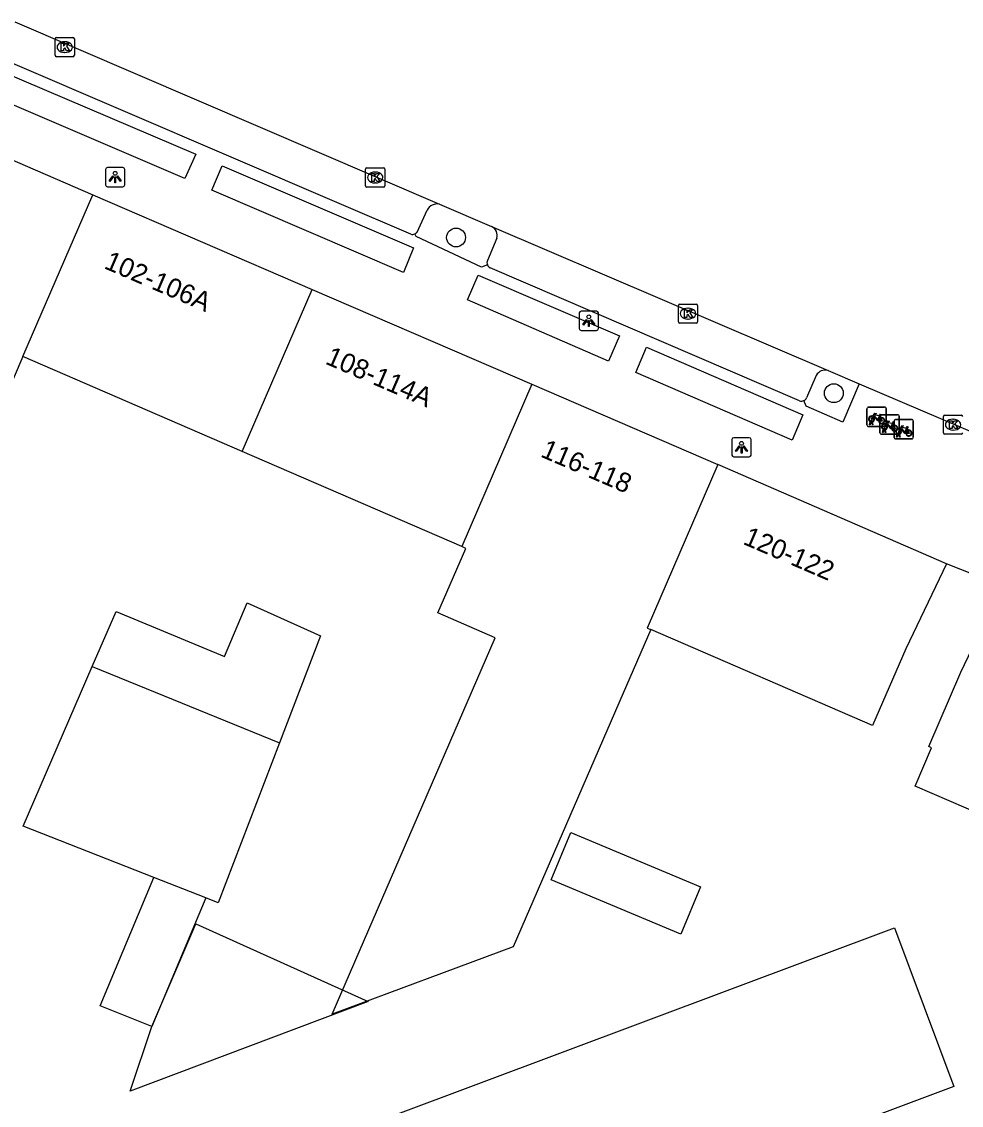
# Model space of a CAD drawing. Extents: x 161801 to 162379, y 382315 to 382832.
# Drawn here: x 162214 to 162262.8, y 382570.8 to 382627.1 of the extents above; entities that cross this region are included whole.
import ezdxf

# ---------------------------------------------------------------- set-up
doc = ezdxf.new("R2010")
doc.units = 0
for name, color, linetype in [('IMGEO_Boom', 7, 'Continuous'), ('IMGEO_Fietsenrek', 7, 'Continuous'), ('IMGEO_Kolk', 7, 'Continuous'), ('IMGEO_Lichtpunt', 7, 'Continuous'), ('IMGEO_Pand', 7, 'Continuous'), ('IMGEO_Pand_nummerreeks', 7, 'Continuous'), ('IMGEO_Pand_vergunning_verleend', 7, 'Continuous'), ('IMGEO_Parkeervlak_open', 7, 'Continuous'), ('IMGEO_Rijbaan_lokaal_gesloten', 7, 'Continuous'), ('IMGEO_Voetpad_open', 7, 'Continuous')]:
    doc.layers.add(name, color=color, linetype=linetype)

msp = doc.modelspace()

# ---------------------------------------------------------------- linework, layer by layer
at = {"layer": 'IMGEO_Boom'}
for centre in [(162236.594, 382615.904), (162256.208, 382607.818)]:
    msp.add_circle(centre, 0.489, dxfattribs=at)
at = {"layer": 'IMGEO_Fietsenrek'}
for p, q in [((162258.004, 382607.092), (162258.845, 382607.092)), ((162258.845, 382607.092), (162258.004, 382607.092)), ((162257.929, 382606.167), (162257.929, 382607.008)), ((162257.929, 382607.008), (162257.929, 382606.167)), ((162258.603, 382605.768), (162258.603, 382606.609)), ((162258.603, 382606.609), (162258.603, 382605.768)), ((162258.616, 382606.641), (162258.652, 382606.546)), ((162258.678, 382606.693), (162259.519, 382606.693)), ((162259.519, 382606.693), (162258.678, 382606.693)), ((162258.929, 382607.017), (162258.929, 382606.176)), ((162258.929, 382606.176), (162258.929, 382607.017)), ((162259.603, 382606.618), (162259.603, 382605.777)), ((162259.603, 382605.777), (162259.603, 382606.618)), ((162258.854, 382606.092), (162258.013, 382606.092)), ((162258.013, 382606.092), (162258.854, 382606.092)), ((162258.056, 382606.176), (162258.095, 382606.336)), ((162258.09, 382606.176), (162258.056, 382606.176)), ((162258.125, 382606.324), (162258.09, 382606.176)), ((162258.167, 382606.348), (162258.166, 382606.352)), ((162258.208, 382606.176), (162258.174, 382606.318)), ((162258.198, 382606.359), (162258.199, 382606.352)), ((162258.206, 382606.322), (162258.241, 382606.176)), ((162258.241, 382606.176), (162258.208, 382606.176)), ((162258.872, 382605.96), (162258.873, 382605.953)), ((162259.29, 382606.242), (162259.326, 382606.147)), ((162259.334, 382605.523), (162259.334, 382606.364)), ((162259.334, 382606.364), (162259.334, 382605.523)), ((162259.409, 382606.448), (162260.25, 382606.448)), ((162260.25, 382606.448), (162259.409, 382606.448)), ((162260.021, 382605.997), (162260.057, 382605.902)), ((162260.334, 382606.373), (162260.334, 382605.532)), ((162260.334, 382605.532), (162260.334, 382606.373)), ((162259.528, 382605.693), (162258.687, 382605.693)), ((162258.687, 382605.693), (162259.528, 382605.693)), ((162258.73, 382605.777), (162258.769, 382605.937)), ((162258.764, 382605.777), (162258.73, 382605.777)), ((162258.799, 382605.925), (162258.764, 382605.777)), ((162258.841, 382605.949), (162258.84, 382605.953)), ((162258.882, 382605.777), (162258.848, 382605.919)), ((162258.88, 382605.923), (162258.915, 382605.777)), ((162258.915, 382605.777), (162258.882, 382605.777)), ((162260.259, 382605.448), (162259.418, 382605.448)), ((162259.418, 382605.448), (162260.259, 382605.448)), ((162259.461, 382605.532), (162259.5, 382605.692)), ((162259.495, 382605.532), (162259.461, 382605.532)), ((162259.53, 382605.68), (162259.495, 382605.532)), ((162259.572, 382605.704), (162259.571, 382605.708)), ((162259.613, 382605.532), (162259.579, 382605.674)), ((162259.603, 382605.715), (162259.604, 382605.708)), ((162259.611, 382605.678), (162259.646, 382605.532)), ((162259.646, 382605.532), (162259.613, 382605.532))]:
    msp.add_line(p, q, dxfattribs=at)
for points in [[(162258.263, 382606.566), (162258.211, 382606.476), (162258.171, 382606.451), (162258.172, 382606.498), (162258.227, 382606.592)], [(162258.242, 382606.618), (162258.337, 382606.782), (162258.423, 382606.768), (162258.425, 382606.759), (162258.369, 382606.748), (162258.342, 382606.703), (162258.598, 382606.662)], [(162258.538, 382606.374), (162258.488, 382606.374), (162258.297, 382606.625), (162258.278, 382606.593)], [(162258.585, 382606.637), (162258.328, 382606.678), (162258.311, 382606.649), (162258.478, 382606.429), (162258.585, 382606.637)], [(162258.633, 382606.539), (162258.603, 382606.616), (162258.494, 382606.398), (162258.537, 382606.398)], [(162258.663, 382606.518), (162258.718, 382606.373), (162258.568, 382606.373)], [(162258.598, 382606.662), (162258.623, 382606.711), (162258.617, 382606.715), (162258.594, 382606.719), (162258.582, 382606.726), (162258.581, 382606.729), (162258.583, 382606.734), (162258.678, 382606.719), (162258.68, 382606.709), (162258.67, 382606.696), (162258.658, 382606.69), (162258.644, 382606.696), (162258.616, 382606.641)], [(162258.567, 382606.398), (162258.687, 382606.397), (162258.643, 382606.511)], [(162258.937, 382606.167), (162258.885, 382606.077), (162258.845, 382606.052), (162258.846, 382606.099), (162258.901, 382606.193)], [(162258.916, 382606.219), (162259.011, 382606.383), (162259.097, 382606.369), (162259.099, 382606.36), (162259.043, 382606.349), (162259.016, 382606.304), (162259.272, 382606.263)], [(162259.212, 382605.975), (162259.162, 382605.975), (162258.971, 382606.226), (162258.952, 382606.194)], [(162259.259, 382606.238), (162259.002, 382606.279), (162258.985, 382606.25), (162259.152, 382606.03), (162259.259, 382606.238)], [(162259.307, 382606.14), (162259.277, 382606.217), (162259.168, 382605.999), (162259.211, 382605.999)], [(162259.241, 382605.999), (162259.361, 382605.998), (162259.317, 382606.112)], [(162259.337, 382606.119), (162259.392, 382605.974), (162259.242, 382605.974)], [(162259.272, 382606.263), (162259.297, 382606.312), (162259.291, 382606.316), (162259.268, 382606.32), (162259.256, 382606.327), (162259.255, 382606.33), (162259.257, 382606.335), (162259.352, 382606.32), (162259.354, 382606.31), (162259.344, 382606.297), (162259.332, 382606.291), (162259.318, 382606.297), (162259.29, 382606.242)], [(162259.647, 382605.974), (162259.742, 382606.138), (162259.828, 382606.124), (162259.83, 382606.115), (162259.774, 382606.104), (162259.747, 382606.059), (162260.003, 382606.018)], [(162259.943, 382605.73), (162259.893, 382605.73), (162259.702, 382605.981), (162259.683, 382605.949)], [(162259.99, 382605.993), (162259.733, 382606.034), (162259.716, 382606.005), (162259.883, 382605.785), (162259.99, 382605.993)], [(162260.038, 382605.895), (162260.008, 382605.972), (162259.899, 382605.754), (162259.942, 382605.754)], [(162260.003, 382606.018), (162260.028, 382606.067), (162260.022, 382606.071), (162259.999, 382606.075), (162259.987, 382606.082), (162259.986, 382606.085), (162259.988, 382606.09), (162260.083, 382606.075), (162260.085, 382606.065), (162260.075, 382606.052), (162260.063, 382606.046), (162260.049, 382606.052), (162260.021, 382605.997)], [(162259.668, 382605.922), (162259.616, 382605.832), (162259.576, 382605.807), (162259.577, 382605.854), (162259.632, 382605.948)], [(162259.972, 382605.754), (162260.092, 382605.753), (162260.048, 382605.867)], [(162260.068, 382605.874), (162260.123, 382605.729), (162259.973, 382605.729)]]:
    msp.add_lwpolyline(points, dxfattribs=at)
for centre, radius, start, end in [((162258.007, 382607.014), 0.0779, 92.4484, 184.2845), ((162258.007, 382607.014), 0.0779, 92.4484, 184.2845), ((162258.851, 382607.014), 0.0779, 2.4484, 94.2845), ((162258.851, 382607.014), 0.0779, 2.4484, 94.2845), ((162258.169, 382606.477), 0.159, 62.6766, 242.1369), ((162258.169, 382606.477), 0.129, 63.3192, 238.903), ((162258.169, 382606.477), 0.129, 283.6043, 43.4302), ((162258.169, 382606.477), 0.159, 283.5766, 46.6042), ((162258.696, 382606.393), 0.159, 113.3408, 178.3217), ((162258.696, 382606.393), 0.159, 187.0065, 105.7708), ((162258.696, 382606.393), 0.129, 188.6715, 104.5883), ((162258.681, 382606.615), 0.0779, 92.4484, 184.2845), ((162258.681, 382606.615), 0.0779, 92.4484, 184.2845), ((162259.525, 382606.615), 0.0779, 2.4484, 94.2845), ((162259.525, 382606.615), 0.0779, 2.4484, 94.2845), ((162258.007, 382606.17), 0.0779, 182.4484, 274.2845), ((162258.007, 382606.17), 0.0779, 182.4484, 274.2845), ((162258.149, 382606.348), 0.0499, 12.8025, 158.6934), ((162258.169, 382606.477), 0.159, 253.9967, 271.7867), ((162258.149, 382606.348), 0.0174, 12.8025, 163.4502), ((162258.169, 382606.477), 0.129, 253.415, 269.0204), ((162258.696, 382606.393), 0.129, 113.923, 177.9556), ((162258.843, 382606.078), 0.159, 62.6766, 242.1369), ((162258.843, 382606.078), 0.129, 63.3192, 238.903), ((162258.823, 382605.949), 0.0499, 12.8025, 158.6934), ((162258.823, 382605.949), 0.0174, 12.8025, 163.4502), ((162258.851, 382606.17), 0.0779, 272.4484, 4.2845), ((162258.851, 382606.17), 0.0779, 272.4484, 4.2845), ((162258.843, 382606.078), 0.129, 283.6043, 43.4302), ((162258.843, 382606.078), 0.159, 283.5766, 46.6042), ((162259.37, 382605.994), 0.159, 113.3408, 178.3217), ((162259.37, 382605.994), 0.159, 187.0065, 105.7708), ((162259.37, 382605.994), 0.129, 113.923, 177.9556), ((162259.37, 382605.994), 0.129, 188.6715, 104.5883), ((162259.412, 382606.37), 0.0779, 92.4484, 184.2845), ((162259.412, 382606.37), 0.0779, 92.4484, 184.2845), ((162259.574, 382605.833), 0.159, 62.6766, 242.1369), ((162259.574, 382605.833), 0.129, 63.3192, 238.903), ((162260.256, 382606.37), 0.0779, 2.4484, 94.2845), ((162260.256, 382606.37), 0.0779, 2.4484, 94.2845), ((162258.681, 382605.771), 0.0779, 182.4484, 274.2845), ((162258.681, 382605.771), 0.0779, 182.4484, 274.2845), ((162258.843, 382606.078), 0.159, 253.9967, 271.7867), ((162258.843, 382606.078), 0.129, 253.415, 269.0204), ((162259.412, 382605.526), 0.0779, 182.4484, 274.2845), ((162259.412, 382605.526), 0.0779, 182.4484, 274.2845), ((162259.554, 382605.704), 0.0499, 12.8025, 158.6934), ((162259.525, 382605.771), 0.0779, 272.4484, 4.2845), ((162259.525, 382605.771), 0.0779, 272.4484, 4.2845), ((162259.574, 382605.833), 0.159, 253.9967, 271.7867), ((162259.554, 382605.704), 0.0174, 12.8025, 163.4502), ((162259.574, 382605.833), 0.129, 253.415, 269.0204), ((162259.574, 382605.833), 0.129, 283.6043, 43.4302), ((162259.574, 382605.833), 0.159, 283.5766, 46.6042), ((162260.101, 382605.749), 0.159, 113.3408, 178.3217), ((162260.101, 382605.749), 0.159, 187.0065, 105.7708), ((162260.101, 382605.749), 0.129, 113.923, 177.9556), ((162260.101, 382605.749), 0.129, 188.6715, 104.5883), ((162260.256, 382605.526), 0.0779, 272.4484, 4.2845), ((162260.256, 382605.526), 0.0779, 272.4484, 4.2845)]:
    msp.add_arc(centre, radius, start, end, dxfattribs=at)
at = {"layer": 'IMGEO_Kolk'}
for p, q in [((162215.778, 382625.366), (162215.778, 382626.218)), ((162215.853, 382626.292), (162216.705, 382626.292)), ((162216.779, 382626.218), (162216.779, 382625.366)), ((162216.266, 382626.072), (162216.291, 382626.072)), ((162216.705, 382625.292), (162215.853, 382625.292)), ((162216.289, 382625.512), (162216.264, 382625.512)), ((162231.971, 382619.519), (162232.823, 382619.519)), ((162231.896, 382618.593), (162231.896, 382619.445)), ((162232.384, 382619.299), (162232.409, 382619.299)), ((162232.897, 382619.445), (162232.897, 382618.593)), ((162232.823, 382618.519), (162231.971, 382618.519)), ((162232.407, 382618.739), (162232.382, 382618.739)), ((162248.137, 382611.523), (162248.137, 382612.375)), ((162248.212, 382612.449), (162249.064, 382612.449)), ((162248.625, 382612.229), (162248.65, 382612.229)), ((162249.138, 382612.375), (162249.138, 382611.523)), ((162248.648, 382611.669), (162248.623, 382611.669)), ((162249.064, 382611.449), (162248.212, 382611.449)), ((162261.901, 382605.757), (162261.901, 382606.609)), ((162261.976, 382606.683), (162262.828, 382606.683)), ((162262.389, 382606.463), (162262.414, 382606.463)), ((162262.828, 382605.683), (162261.976, 382605.683)), ((162262.412, 382605.903), (162262.387, 382605.903))]:
    msp.add_line(p, q, dxfattribs=at)
for points in [[(162215.778, 382625.366), (162215.778, 382626.218)], [(162215.853, 382626.292), (162216.705, 382626.292)], [(162216.779, 382626.218), (162216.779, 382625.366)], [(162216.099, 382625.992), (162216.222, 382625.992), (162216.222, 382625.841), (162216.352, 382625.992), (162216.516, 382625.992), (162216.37, 382625.841), (162216.523, 382625.592), (162216.371, 382625.592), (162216.286, 382625.756), (162216.222, 382625.689), (162216.222, 382625.592), (162216.099, 382625.592), (162216.099, 382625.992)], [(162216.705, 382625.292), (162215.853, 382625.292)], [(162231.971, 382619.519), (162232.823, 382619.519)], [(162231.896, 382618.593), (162231.896, 382619.445)], [(162232.217, 382619.219), (162232.34, 382619.219), (162232.34, 382619.068), (162232.47, 382619.219), (162232.634, 382619.219), (162232.488, 382619.068), (162232.641, 382618.819), (162232.489, 382618.819), (162232.404, 382618.983), (162232.34, 382618.916), (162232.34, 382618.819), (162232.217, 382618.819), (162232.217, 382619.219)], [(162232.897, 382619.445), (162232.897, 382618.593)], [(162232.823, 382618.519), (162231.971, 382618.519)], [(162248.137, 382611.523), (162248.137, 382612.375)], [(162248.212, 382612.449), (162249.064, 382612.449)], [(162248.458, 382612.149), (162248.581, 382612.149), (162248.581, 382611.998), (162248.711, 382612.149), (162248.875, 382612.149), (162248.729, 382611.998), (162248.882, 382611.749), (162248.73, 382611.749), (162248.645, 382611.913), (162248.581, 382611.846), (162248.581, 382611.749), (162248.458, 382611.749), (162248.458, 382612.149)], [(162249.138, 382612.375), (162249.138, 382611.523)], [(162249.064, 382611.449), (162248.212, 382611.449)], [(162261.901, 382605.757), (162261.901, 382606.609)], [(162261.976, 382606.683), (162262.828, 382606.683)], [(162262.222, 382606.383), (162262.345, 382606.383), (162262.345, 382606.232), (162262.475, 382606.383), (162262.639, 382606.383), (162262.493, 382606.232), (162262.646, 382605.983), (162262.494, 382605.983), (162262.409, 382606.147), (162262.345, 382606.08), (162262.345, 382605.983), (162262.222, 382605.983), (162262.222, 382606.383)], [(162262.828, 382605.683), (162261.976, 382605.683)]]:
    msp.add_lwpolyline(points, dxfattribs=at)
for centre, start, end in [((162215.855, 382626.216), 91.552, 178.448), ((162215.855, 382626.216), 91.552, 178.448), ((162216.703, 382626.216), 1.552, 88.448), ((162216.703, 382626.216), 1.552, 88.448), ((162215.855, 382625.368), 181.552, 268.448), ((162215.855, 382625.368), 181.552, 268.448), ((162216.703, 382625.368), 271.552, 358.448), ((162216.703, 382625.368), 271.552, 358.448), ((162231.973, 382619.443), 91.552, 178.448), ((162231.973, 382619.443), 91.552, 178.448), ((162232.821, 382619.443), 1.552, 88.448), ((162232.821, 382619.443), 1.552, 88.448), ((162231.973, 382618.595), 181.552, 268.448), ((162231.973, 382618.595), 181.552, 268.448), ((162232.821, 382618.595), 271.552, 358.448), ((162232.821, 382618.595), 271.552, 358.448), ((162248.214, 382612.373), 91.552, 178.448), ((162248.214, 382612.373), 91.552, 178.448), ((162249.062, 382612.373), 1.552, 88.448), ((162249.062, 382612.373), 1.552, 88.448), ((162248.214, 382611.525), 181.552, 268.448), ((162248.214, 382611.525), 181.552, 268.448), ((162249.062, 382611.525), 271.552, 358.448), ((162249.062, 382611.525), 271.552, 358.448), ((162261.978, 382606.607), 91.552, 178.448), ((162261.978, 382606.607), 91.552, 178.448), ((162262.826, 382606.607), 1.552, 88.448), ((162262.826, 382606.607), 1.552, 88.448), ((162261.978, 382605.759), 181.552, 268.448), ((162261.978, 382605.759), 181.552, 268.448), ((162262.826, 382605.759), 271.552, 358.448), ((162262.826, 382605.759), 271.552, 358.448)]:
    msp.add_arc(centre, 0.0765, start, end, dxfattribs=at)
for centre, major_axis, ratio, start_param, end_param in [((162216.265, 382625.792), (-0.387, 0.002), 0.722429, 4.712389, 7.853982), ((162216.29, 382625.792), (-0.39, 0.002), 0.717154, 1.570796, 4.712389), ((162232.383, 382619.019), (-0.387, 0.002), 0.722429, 4.712389, 7.853982), ((162232.408, 382619.019), (-0.39, 0.002), 0.717154, 1.570796, 4.712389), ((162248.624, 382611.949), (-0.387, 0.002), 0.722429, 4.712389, 7.853982), ((162248.649, 382611.949), (-0.39, 0.002), 0.717154, 1.570796, 4.712389), ((162262.388, 382606.183), (-0.387, 0.002), 0.722429, 4.712389, 7.853982), ((162262.413, 382606.183), (-0.39, 0.002), 0.717154, 1.570796, 4.712389)]:
    msp.add_ellipse(centre, major_axis=major_axis, ratio=ratio, start_param=start_param, end_param=end_param, dxfattribs=at)
at = {"layer": 'IMGEO_Lichtpunt'}
for p, q in [((162219.299, 382619.537), (162218.491, 382619.537)), ((162219.299, 382619.537), (162218.491, 382619.537)), ((162218.397, 382619.442), (162218.397, 382618.635)), ((162218.397, 382619.442), (162218.397, 382618.635)), ((162219.393, 382618.635), (162219.393, 382619.442)), ((162219.393, 382618.635), (162219.393, 382619.442)), ((162218.491, 382618.541), (162219.299, 382618.541)), ((162218.491, 382618.541), (162219.299, 382618.541)), ((162242.989, 382611.983), (162242.989, 382611.176)), ((162242.989, 382611.983), (162242.989, 382611.176)), ((162243.891, 382612.078), (162243.083, 382612.078)), ((162243.891, 382612.078), (162243.083, 382612.078)), ((162243.985, 382611.176), (162243.985, 382611.983)), ((162243.985, 382611.176), (162243.985, 382611.983)), ((162243.083, 382611.082), (162243.891, 382611.082)), ((162243.083, 382611.082), (162243.891, 382611.082)), ((162250.919, 382605.413), (162250.919, 382604.606)), ((162250.919, 382605.413), (162250.919, 382604.606)), ((162251.821, 382605.508), (162251.013, 382605.508)), ((162251.821, 382605.508), (162251.013, 382605.508)), ((162251.915, 382604.606), (162251.915, 382605.413)), ((162251.915, 382604.606), (162251.915, 382605.413)), ((162251.013, 382604.512), (162251.821, 382604.512)), ((162251.013, 382604.512), (162251.821, 382604.512))]:
    msp.add_line(p, q, dxfattribs=at)
for points in [[(162218.771, 382619.106), (162218.81, 382619.078), (162218.622, 382618.816), (162218.584, 382618.843), (162218.771, 382619.106)], [(162218.873, 382619.058), (162218.92, 382619.058), (162218.92, 382618.736), (162218.873, 382618.736), (162218.873, 382619.058)], [(162218.983, 382619.078), (162219.021, 382619.105), (162219.208, 382618.843), (162219.169, 382618.815), (162218.983, 382619.078)], [(162243.363, 382611.647), (162243.402, 382611.619), (162243.214, 382611.357), (162243.176, 382611.384), (162243.363, 382611.647)], [(162243.465, 382611.599), (162243.512, 382611.599), (162243.512, 382611.277), (162243.465, 382611.277), (162243.465, 382611.599)], [(162243.575, 382611.619), (162243.613, 382611.646), (162243.8, 382611.384), (162243.761, 382611.356), (162243.575, 382611.619)], [(162251.293, 382605.077), (162251.332, 382605.049), (162251.144, 382604.787), (162251.106, 382604.814), (162251.293, 382605.077)], [(162251.395, 382605.029), (162251.442, 382605.029), (162251.442, 382604.707), (162251.395, 382604.707), (162251.395, 382605.029)], [(162251.505, 382605.049), (162251.543, 382605.076), (162251.73, 382604.814), (162251.691, 382604.786), (162251.505, 382605.049)]]:
    msp.add_lwpolyline(points, dxfattribs=at)
for centre in [(162218.896, 382619.24), (162243.488, 382611.781), (162251.418, 382605.211)]:
    msp.add_circle(centre, 0.0994, dxfattribs=at)
for centre, start, end in [((162218.491, 382619.442), 90, 180), ((162218.491, 382619.442), 90, 180), ((162219.299, 382619.442), 0, 90), ((162219.299, 382619.442), 0, 90), ((162218.491, 382618.635), 180, 270), ((162218.491, 382618.635), 180, 270), ((162219.299, 382618.635), 270, 0), ((162219.299, 382618.635), 270, 360), ((162243.083, 382611.983), 90, 180), ((162243.083, 382611.983), 90, 180), ((162243.891, 382611.983), 0, 90), ((162243.891, 382611.983), 0, 90), ((162243.083, 382611.176), 180, 270), ((162243.083, 382611.176), 180, 270), ((162243.891, 382611.176), 270, 0), ((162243.891, 382611.176), 270, 360), ((162251.013, 382605.413), 90, 180), ((162251.013, 382605.413), 90, 180), ((162251.821, 382605.413), 0, 90), ((162251.821, 382605.413), 0, 90), ((162251.013, 382604.606), 180, 270), ((162251.013, 382604.606), 180, 270), ((162251.821, 382604.606), 270, 0), ((162251.821, 382604.606), 270, 360)]:
    msp.add_arc(centre, 0.0946, start, end, dxfattribs=at)
at = {"layer": 'IMGEO_Pand'}
for points in [[(162208.854, 382621.959), (162217.734, 382618.126)], [(162214.108, 382609.725), (162217.734, 382618.126)], [(162217.734, 382618.126), (162229.119, 382613.211)], [(162225.486, 382604.794), (162229.119, 382613.211)], [(162229.119, 382613.211), (162240.534, 382608.284)], [(162214.108, 382609.725), (162212.678, 382606.426), (162208.675, 382608.161), (162204.087, 382610.149)], [(162225.486, 382604.794), (162214.108, 382609.725)], [(162240.534, 382608.284), (162236.893, 382599.851)], [(162240.534, 382608.284), (162250.193, 382604.115)], [(162236.893, 382599.851), (162225.486, 382604.794)], [(162250.193, 382604.115), (162246.525, 382595.619), (162246.707, 382595.54)], [(162262.061, 382598.95), (162250.193, 382604.115)], [(162246.707, 382595.54), (162245.276, 382592.24), (162239.564, 382579.067), (162230.156, 382575.563), (162238.632, 382595.119), (162235.65, 382596.412), (162237.101, 382599.761), (162236.893, 382599.851)], [(162262.061, 382598.95), (162259.947, 382594.543), (162258.218, 382590.552), (162246.707, 382595.54)], [(162288.531, 382587.678), (162286.557, 382583.039), (162284.032, 382577.205), (162279.872, 382579.006), (162278.126, 382579.735), (162266.42, 382584.801), (162263.954, 382585.878), (162260.424, 382587.406), (162261.288, 382589.402), (162261.134, 382589.469), (162262.802, 382593.322), (162264.942, 382597.806)], [(162217.707, 382593.617), (162218.951, 382596.487), (162224.575, 382594.142), (162225.75, 382596.93), (162229.557, 382595.219), (162227.423, 382589.653)], [(162220.912, 382582.668), (162214.119, 382585.338), (162217.707, 382593.617)], [(162217.707, 382593.617), (162227.423, 382589.653)], [(162227.423, 382589.653), (162224.244, 382581.359), (162223.602, 382581.611)], [(162242.558, 382584.999), (162249.289, 382582.174), (162248.261, 382579.725), (162241.53, 382582.551), (162242.558, 382584.999)], [(162223.602, 382581.611), (162220.802, 382574.936), (162218.113, 382575.994), (162220.912, 382582.668)], [(162223.602, 382581.611), (162220.912, 382582.668)]]:
    msp.add_lwpolyline(points, dxfattribs=at)
at = {"layer": 'IMGEO_Pand_vergunning_verleend'}
for points in [[(162219.681, 382571.572), (162220.802, 382574.936), (162223.089, 382580.252), (162232.033, 382576.233), (162219.681, 382571.572)], [(162233.442, 382570.34), (162259.36, 382580.047), (162262.443, 382571.813), (162236.525, 382562.106), (162233.442, 382570.34)]]:
    msp.add_lwpolyline(points, dxfattribs=at)
at = {"layer": 'IMGEO_Parkeervlak_open'}
for points in [[(162234.576, 382616.185), (162235.09, 382617.324)], [(162238.708, 382615.861), (162238.22, 382614.71)], [(162255.298, 382608.737), (162254.797, 382607.57)]]:
    msp.add_lwpolyline(points, dxfattribs=at)
for centre, radius, start, end in [((162235.629, 382617.039), 0.61, 79.6112, 152.1692), ((162234.326, 382616.383), 0.319, 292.9123, 321.6956), ((162238.218, 382616.015), 0.513, 342.5483, 64.1628), ((162238.495, 382614.6), 0.296, 158.2871, 202.736), ((162255.752, 382608.506), 0.51, 71.835, 153.0192), ((162254.523, 382607.724), 0.314, 294.0277, 330.6368)]:
    msp.add_arc(centre, radius, start, end, dxfattribs=at)
at = {"layer": 'IMGEO_Rijbaan_lokaal_gesloten'}
for points in [[(162213.679, 382627.112), (162235.739, 382617.639)], [(162235.739, 382617.639), (162238.442, 382616.477)], [(162238.442, 382616.477), (162255.911, 382608.99)], [(162255.911, 382608.99), (162257.528, 382608.307)], [(162257.528, 382608.307), (162269.376, 382603.243)]]:
    msp.add_lwpolyline(points, dxfattribs=at)
at = {"layer": 'IMGEO_Voetpad_open'}
for points in [[(162212.448, 382623.284), (162212.974, 382624.543), (162223.092, 382620.232), (162222.519, 382618.968), (162212.448, 382623.284)], [(162234.242, 382616.077), (162230.532, 382617.668), (162213.588, 382624.937)], [(162233.864, 382614.081), (162223.921, 382618.362), (162224.459, 382619.631), (162234.387, 382615.372), (162233.864, 382614.081)], [(162238.222, 382614.486), (162237.909, 382614.355), (162234.516, 382615.954), (162234.45, 382616.089)], [(162244.515, 382609.488), (162237.197, 382612.666), (162237.747, 382613.949), (162245.085, 382610.803), (162244.515, 382609.488)], [(162254.425, 382607.424), (162238.367, 382614.336)], [(162254.039, 382605.381), (162245.928, 382608.892), (162246.477, 382610.203), (162254.596, 382606.7), (162254.039, 382605.381)], [(162257.528, 382608.307), (162256.682, 382606.305), (162254.766, 382607.137), (162254.651, 382607.437)], [(162264.942, 382597.806), (162262.061, 382598.95)]]:
    msp.add_lwpolyline(points, dxfattribs=at)
for centre, radius, start, end in [((162234.329, 382616.374), 0.31, 253.6656, 292.9381), ((162238.496, 382614.606), 0.3, 203.658, 244.3999), ((162254.521, 382607.732), 0.322, 252.7371, 293.8472)]:
    msp.add_arc(centre, radius, start, end, dxfattribs=at)

# ---------------------------------------------------------------- texts
at = {"layer": 'IMGEO_Pand_nummerreeks'}
for s, rotation, p in [('102-106A', 336.6521, (162218.271, 382614.322)), ('108-114A', 336.6521, (162229.755, 382609.364)), ('116-118', 336.6526, (162240.931, 382604.54)), ('120-122', 336.652, (162251.443, 382600.003))]:
    msp.add_text(s, height=1, rotation=rotation, dxfattribs=at).set_placement(p)

doc.saveas('drawing.dxf')
